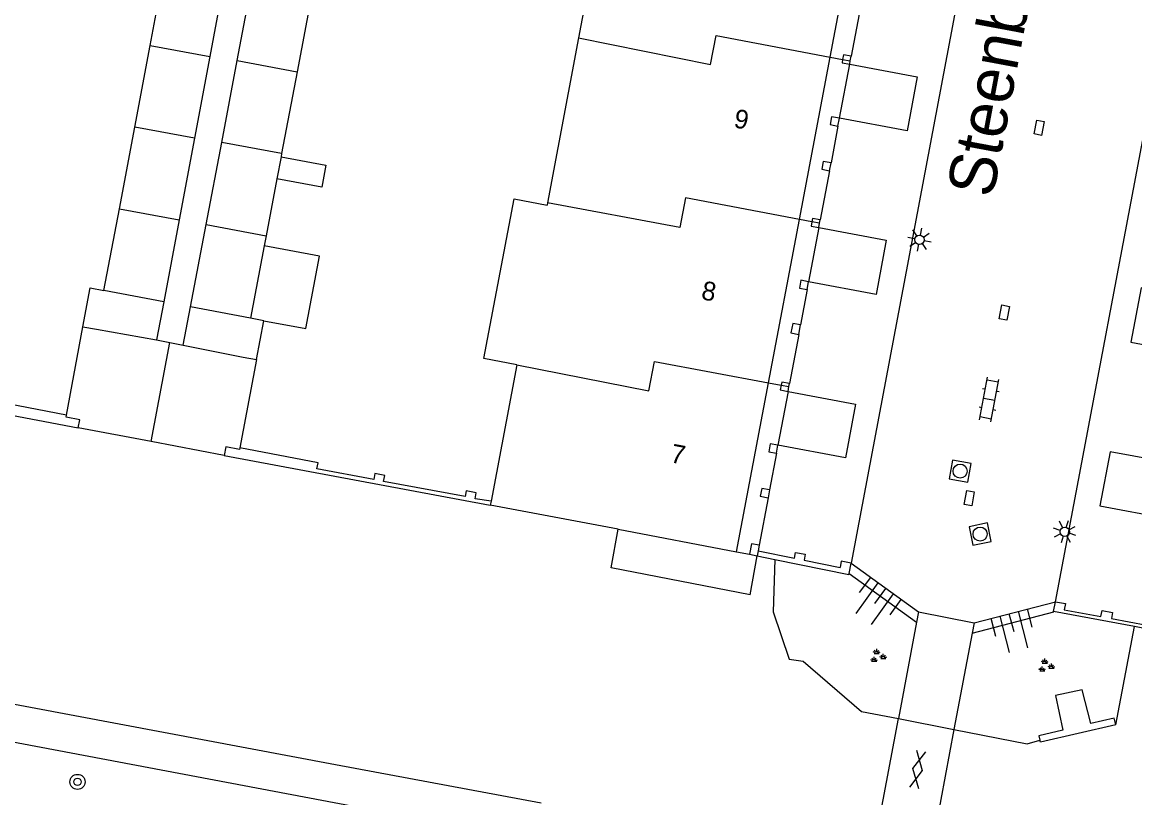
# Model space of a CAD drawing. Extents: x 124000 to 128010, y 398999 to 403000.
# Drawn here: x 126679.1 to 126738.3, y 399098.7 to 399140 of the extents above; entities that cross this region are included whole.
import ezdxf

# ---------------------------------------------------------------- set-up
doc = ezdxf.new("R2010")
doc.units = 0
for name, color, linetype in [('gg-afsc-muur', 7, 'Continuous'), ('gg-anno-huisnummerreeks BGT', 7, 'Continuous'), ('gg-anno-openbare ruimte label', 7, 'Continuous'), ('gg-bbg-bijgebouw', 7, 'Continuous'), ('gg-bbg-gedigitaliseerde bebouwing', 7, 'Continuous'), ('gg-bbg-gedigitaliseerde bijgebouw', 7, 'Continuous'), ('gg-bbg-hoofdgebouw', 7, 'Continuous'), ('gg-bbg-luifel en loopbrug', 7, 'Continuous'), ('gg-bbg-onder overbouw', 7, 'Continuous'), ('gg-bbg-pand overbouw', 7, 'Continuous'), ('gg-bbg-pilaar onder overbouw', 7, 'Continuous'), ('gg-bbg-pilaar pand', 7, 'Continuous'), ('gg-bbg-tussenscheiding', 7, 'Continuous'), ('gg-bbg-tussenscheiding niveau 01', 7, 'Continuous'), ('gg-knt-verharding', 7, 'Continuous'), ('gg-kntw-beschoeiing', 7, 'Continuous'), ('gg-kntw-kademuur', 7, 'Continuous'), ('gg-kwrk-kunstwerk niveau 01', 7, 'Continuous'), ('gg-kwrk-uitstroombak niveau min 01', 7, 'Continuous'), ('gt-grn-groengrens', 7, 'Continuous'), ('gt-symb-boom', 7, 'Continuous'), ('gt-symb-gesloten verharding', 7, 'Continuous'), ('gt-symb-groenvak', 7, 'Continuous'), ('gt-symb-klinker verharding', 7, 'Continuous'), ('gt-symb-kolk center center', 7, 'Continuous'), ('gt-symb-lichtmast', 7, 'Continuous'), ('gt-symb-rioolschacht', 7, 'Continuous'), ('gt-symb-talud symbool', 7, 'Continuous')]:
    doc.layers.add(name, color=color, linetype=linetype)

# ---------------------------------------------------------------- blocks, each defined once
blk = doc.blocks.new('gt0-LMAST')
at = {"layer": 'gt-symb-lichtmast'}
for p, q in [((-0.005, 0.246), (-0.005, 0.621)), ((-0.182, 0.173), (-0.447, 0.438)), ((0.172, 0.173), (0.437, 0.438)), ((-0.255, -0.004), (-0.63, -0.004)), ((-0.182, -0.181), (-0.447, -0.446)), ((-0.005, -0.254), (-0.005, -0.629)), ((0.437, -0.446), (0.172, -0.181)), ((0.245, -0.004), (0.62, -0.004))]:
    blk.add_line(p, q, dxfattribs=at)
blk.add_circle((-0.005, -0.004), 0.25, dxfattribs=at)
blk = doc.blocks.new('gt0-KOLKCC')
at = {"layer": 'gt-symb-kolk center center'}
blk.add_lwpolyline([(-0.375, 0.2), (0.375, 0.2), (0.375, -0.2), (-0.375, -0.2)], close=True, dxfattribs=at)
blk = doc.blocks.new('gt0-BOOM')
at = {"layer": 'gt-symb-boom'}
for radius in [0.4, 0.2]:
    blk.add_circle((0, 0), radius, dxfattribs=at)
blk = doc.blocks.new('gt0-KL1')
at = {"layer": 'gt-symb-klinker verharding'}
for p, q in [((-1.15, 0.3), (1.15, 0.3)), ((-1, -0.3), (-1, 0.3)), ((-0.5, 0.3), (-0.5, 0.45)), ((0, -0.3), (0, 0.3)), ((0.5, 0.3), (0.5, 0.45)), ((1, -0.3), (1, 0.3)), ((-1.15, -0.3), (1.15, -0.3)), ((-0.5, -0.45), (-0.5, -0.3)), ((0.5, -0.45), (0.5, -0.3))]:
    blk.add_line(p, q, dxfattribs=at)
blk = doc.blocks.new('gt0-RS')
at = {"layer": 'gt-symb-rioolschacht'}
blk.add_lwpolyline([(-0.5, -0.5), (0.5, -0.5), (0.5, 0.5), (-0.5, 0.5)], close=True, dxfattribs=at)
blk.add_circle((0, 0), 0.375, dxfattribs=at)
blk = doc.blocks.new('gt0-GESVH1')
at = {"layer": 'gt-symb-gesloten verharding'}
for p, q in [((-0.992, -0.261), (0.008, 0.239)), ((0.008, -0.261), (-0.992, 0.239)), ((0.008, 0.239), (1.008, -0.261)), ((1.008, 0.239), (0.008, -0.261))]:
    blk.add_line(p, q, dxfattribs=at)
blk = doc.blocks.new('gt0-TALUD_1')
at = {"layer": 'gt-symb-talud symbool'}
for p, q in [((-1, -1), (-1, 0)), ((-0.5, -2), (-0.5, 0)), ((0, -1), (0, 0)), ((0.5, -2), (0.5, 0)), ((1, -1), (1, 0))]:
    blk.add_line(p, q, dxfattribs=at)
blk = doc.blocks.new('gt0-GRVAK')
at = {"layer": 'gt-symb-groenvak'}
for p, q in [((-0.11, 0.189), (-0.228, 0.24)), ((-0.182, 0.153), (0.088, 0.153)), ((-0.091, 0.211), (-0.156, 0.322)), ((-0.047, 0.214), (-0.047, 0.393)), ((-0.004, 0.211), (0.061, 0.322)), ((0.015, 0.189), (0.133, 0.24)), ((0.262, -0.052), (0.197, 0.059)), ((0.305, -0.049), (0.305, 0.13)), ((0.349, -0.052), (0.414, 0.059)), ((-0.245, -0.228), (-0.363, -0.177)), ((-0.318, -0.264), (-0.047, -0.264)), ((-0.226, -0.206), (-0.291, -0.095)), ((-0.183, -0.203), (-0.183, -0.024)), ((-0.139, -0.206), (-0.074, -0.095)), ((-0.12, -0.228), (-0.002, -0.177)), ((0.243, -0.074), (0.125, -0.023)), ((0.17, -0.11), (0.441, -0.11)), ((0.368, -0.074), (0.486, -0.023))]:
    blk.add_line(p, q, dxfattribs=at)

msp = doc.modelspace()

# ---------------------------------------------------------------- linework, layer by layer
at = {"layer": 'gg-afsc-muur'}
for p, q in [((126719.141, 399111.407), (126723.075, 399110.606)), ((126720.689, 399111.375), (126722.604, 399110.986)), ((126723.087, 399110.667), (126723.192, 399111.208)), ((126723.075, 399110.606), (126723.087, 399110.667)), ((126733.952, 399108.645), (126734.049, 399109.162)), ((126738.243, 399107.841), (126733.952, 399108.645))]:
    msp.add_line(p, q, dxfattribs=at)
for points in [[(126681.496, 399119.082), (126677.347, 399119.87), (126677.285, 399119.546), (126674.107, 399120.141), (126674.164, 399120.471), (126673.651, 399120.556), (126673.597, 399120.23), (126670.209, 399120.886), (126670.267, 399121.207), (126669.747, 399121.295), (126669.692, 399120.97), (126666.052, 399121.679)], [(126704.06, 399114.5), (126703.213, 399114.633), (126703.26, 399114.958), (126702.735, 399115.064), (126702.686, 399114.749), (126698.345, 399115.549), (126698.413, 399115.872), (126697.891, 399115.981), (126697.829, 399115.657), (126694.804, 399116.229), (126694.875, 399116.541), (126690.707, 399117.344)], [(126718.3, 399112.161), (126717.901, 399112.236), (126717.797, 399111.681)], [(126718.248, 399111.872), (126720.178, 399111.479), (126720.237, 399111.787)], [(126720.237, 399111.787), (126720.751, 399111.682), (126720.689, 399111.375)], [(126723.192, 399111.208), (126722.667, 399111.31), (126722.604, 399110.986)], [(126734.049, 399109.162), (126734.58, 399109.063), (126734.518, 399108.735), (126736.465, 399108.37)], [(126736.465, 399108.37), (126736.533, 399108.697), (126737.085, 399108.593), (126737.023, 399108.266), (126738.904, 399107.913)]]:
    msp.add_lwpolyline(points, dxfattribs=at)
at = {"layer": 'gg-bbg-bijgebouw'}
for p, q in [((126685.128, 399134.399), (126685.947, 399138.742)), ((126689.107, 399138.148), (126688.292, 399133.804)), ((126689.745, 399133.587), (126690.568, 399137.935)), ((126693.748, 399137.337), (126692.929, 399132.988)), ((126683.49, 399125.713), (126684.309, 399130.056)), ((126687.478, 399129.46), (126686.663, 399125.115)), ((126688.088, 399124.835), (126688.917, 399129.211)), ((126692.105, 399128.611), (126692.006, 399128.087)), ((126692.006, 399128.087), (126691.281, 399124.234)), ((126681.496, 399119.082), (126682.374, 399123.784)), ((126686.281, 399123.081), (126686.993, 399122.944)), ((126686.993, 399122.944), (126687.704, 399122.807)), ((126691.597, 399122.045), (126690.707, 399117.344)), ((126686.001, 399117.678), (126682.123, 399118.411)), ((126689.879, 399116.945), (126686.001, 399117.678))]:
    msp.add_line(p, q, dxfattribs=at)
for points in [[(126682.374, 399123.784), (126683.101, 399123.647), (126686.281, 399123.081)], [(126687.704, 399122.807), (126690.893, 399122.17), (126691.597, 399122.045)], [(126682.123, 399118.411), (126682.202, 399118.833), (126681.475, 399118.969), (126681.496, 399119.082)], [(126690.707, 399117.344), (126690.69, 399117.253), (126689.963, 399117.391), (126689.879, 399116.945)]]:
    msp.add_lwpolyline(points, dxfattribs=at)
at = {"layer": 'gg-bbg-gedigitaliseerde bebouwing'}
msp.add_lwpolyline([(126705.436, 399121.752), (126703.676, 399122.086), (126705.289, 399130.588), (126707.039, 399130.256)], dxfattribs=at)
at = {"layer": 'gg-bbg-gedigitaliseerde bijgebouw'}
for p, q in [((126685.947, 399138.742), (126689.107, 399138.148)), ((126690.568, 399137.935), (126693.748, 399137.337)), ((126688.292, 399133.804), (126685.128, 399134.399)), ((126692.929, 399132.988), (126689.745, 399133.587)), ((126684.309, 399130.056), (126687.478, 399129.46)), ((126688.917, 399129.211), (126692.105, 399128.611)), ((126686.663, 399125.115), (126683.49, 399125.713)), ((126691.281, 399124.234), (126688.088, 399124.835))]:
    msp.add_line(p, q, dxfattribs=at)
at = {"layer": 'gg-bbg-hoofdgebouw'}
for p, q in [((126708.712, 399139.147), (126707.062, 399130.38)), ((126707.062, 399130.38), (126707.039, 399130.256)), ((126705.436, 399121.752), (126704.06, 399114.5)), ((126704.06, 399114.5), (126704.02, 399114.287)), ((126710.807, 399113.011), (126704.02, 399114.287))]:
    msp.add_line(p, q, dxfattribs=at)
msp.add_lwpolyline([(126712.386, 399147.269), (126710.3, 399147.585), (126708.712, 399139.147)], dxfattribs=at)
at = {"layer": 'gg-bbg-luifel en loopbrug'}
for p, q in [((126685.947, 399138.742), (126686.766, 399143.085)), ((126689.921, 399142.491), (126689.107, 399138.148)), ((126690.568, 399137.935), (126691.391, 399142.283)), ((126694.566, 399141.686), (126693.748, 399137.337)), ((126684.309, 399130.056), (126685.128, 399134.399)), ((126688.292, 399133.804), (126687.478, 399129.46)), ((126688.917, 399129.211), (126689.745, 399133.587)), ((126692.898, 399132.825), (126692.678, 399131.654)), ((126692.929, 399132.988), (126692.898, 399132.825)), ((126692.678, 399131.654), (126692.105, 399128.611)), ((126686.663, 399125.115), (126686.281, 399123.081)), ((126687.704, 399122.807), (126688.088, 399124.835)), ((126691.982, 399124.103), (126691.281, 399124.234)), ((126691.597, 399122.045), (126691.982, 399124.103))]:
    msp.add_line(p, q, dxfattribs=at)
for points in [[(126723.118, 399137.747), (126726.706, 399137.077), (126726.169, 399134.201), (126722.574, 399134.872)], [(126692.898, 399132.825), (126695.282, 399132.376), (126695.062, 399131.206), (126692.678, 399131.654)], [(126721.476, 399129.052), (126725.064, 399128.382), (126724.527, 399125.505), (126720.934, 399126.176)], [(126691.982, 399124.103), (126694.211, 399123.682), (126694.939, 399127.533), (126692.006, 399128.087)], [(126682.374, 399123.784), (126682.76, 399125.849), (126683.49, 399125.713)], [(126742.189, 399125.174), (126738.601, 399125.845), (126738.063, 399122.964), (126741.644, 399122.295)], [(126719.843, 399120.344), (126723.431, 399119.674), (126722.896, 399116.807), (126719.303, 399117.478)], [(126740.544, 399116.468), (126736.956, 399117.139), (126736.418, 399114.259), (126740.001, 399113.589)]]:
    msp.add_lwpolyline(points, dxfattribs=at)
at = {"layer": 'gg-bbg-onder overbouw'}
for p, q in [((126722.085, 399138.125), (126723.744, 399146.899)), ((126720.452, 399129.488), (126722.085, 399138.125)), ((126718.808, 399120.802), (126720.452, 399129.488)), ((126717.11, 399111.821), (126718.808, 399120.802)), ((126710.807, 399113.011), (126717.11, 399111.821))]:
    msp.add_line(p, q, dxfattribs=at)
at = {"layer": 'gg-bbg-pand overbouw'}
for p, q in [((126723.688, 399140.784), (126723.194, 399138.163)), ((126722.574, 399134.872), (126723.118, 399137.747)), ((126722.495, 399134.456), (126722.125, 399132.494)), ((126722.047, 399132.078), (126721.555, 399129.468)), ((126721.476, 399129.052), (126720.934, 399126.176)), ((126720.862, 399125.759), (126720.509, 399123.885)), ((126720.413, 399123.373), (126719.921, 399120.76)), ((126719.843, 399120.344), (126719.303, 399117.478)), ((126719.225, 399117.062), (126718.856, 399115.104)), ((126718.777, 399114.688), (126718.3, 399112.161)), ((126718.248, 399111.872), (126718.198, 399111.599)), ((126718.3, 399112.161), (126718.248, 399111.872)), ((126717.825, 399109.532), (126718.198, 399111.599))]:
    msp.add_line(p, q, dxfattribs=at)
msp.add_lwpolyline([(126717.825, 399109.532), (126710.434, 399110.959), (126710.807, 399113.011)], dxfattribs=at)
at = {"layer": 'gg-bbg-pilaar onder overbouw'}
for points in [[(126722.74, 399138.002), (126722.709, 399137.824), (126723.118, 399137.747)], [(126723.194, 399138.163), (126722.781, 399138.241), (126722.74, 399138.002)], [(126722.574, 399134.872), (126722.154, 399134.951), (126722.082, 399134.534), (126722.495, 399134.456)], [(126722.125, 399132.494), (126721.706, 399132.573), (126721.634, 399132.156), (126722.047, 399132.078)], [(126721.555, 399129.468), (126721.135, 399129.547), (126721.104, 399129.365)], [(126721.104, 399129.365), (126721.063, 399129.13), (126721.476, 399129.052)], [(126720.934, 399126.176), (126720.521, 399126.254), (126720.449, 399125.837), (126720.862, 399125.759)], [(126720.509, 399123.885), (126720.09, 399123.964), (126719.994, 399123.452), (126720.413, 399123.373)], [(126719.477, 399120.676), (126719.43, 399120.422), (126719.843, 399120.344)], [(126719.921, 399120.76), (126719.508, 399120.838), (126719.477, 399120.676)], [(126719.303, 399117.478), (126718.89, 399117.556), (126718.812, 399117.14), (126719.225, 399117.062)], [(126718.856, 399115.104), (126718.443, 399115.182), (126718.365, 399114.769), (126718.777, 399114.688)]]:
    msp.add_lwpolyline(points, dxfattribs=at)
at = {"layer": 'gg-bbg-pilaar pand'}
for p, q in [((126723.118, 399137.747), (126723.15, 399137.924)), ((126723.15, 399137.924), (126723.194, 399138.163)), ((126722.495, 399134.456), (126722.574, 399134.872)), ((126722.047, 399132.078), (126722.125, 399132.494)), ((126721.476, 399129.052), (126721.521, 399129.286)), ((126721.521, 399129.286), (126721.555, 399129.468)), ((126720.862, 399125.759), (126720.934, 399126.176)), ((126720.413, 399123.373), (126720.509, 399123.885)), ((126719.891, 399120.598), (126719.921, 399120.76)), ((126719.843, 399120.344), (126719.891, 399120.598)), ((126719.225, 399117.062), (126719.303, 399117.478)), ((126718.856, 399115.104), (126718.777, 399114.688))]:
    msp.add_line(p, q, dxfattribs=at)
at = {"layer": 'gg-bbg-tussenscheiding'}
msp.add_line((126686.001, 399117.678), (126686.993, 399122.944), dxfattribs=at)
for points in [[(126708.712, 399139.147), (126715.729, 399137.722), (126716.021, 399139.265), (126722.085, 399138.125)], [(126720.452, 399129.488), (126714.387, 399130.629), (126714.091, 399129.057), (126707.062, 399130.38)], [(126705.436, 399121.752), (126712.45, 399120.381), (126712.745, 399121.943), (126718.808, 399120.802)]]:
    msp.add_lwpolyline(points, dxfattribs=at)
at = {"layer": 'gg-bbg-tussenscheiding niveau 01'}
for p, q in [((126722.085, 399138.125), (126722.74, 399138.002)), ((126722.74, 399138.002), (126723.15, 399137.924)), ((126721.104, 399129.365), (126720.452, 399129.488)), ((126721.521, 399129.286), (126721.104, 399129.365)), ((126718.808, 399120.802), (126719.477, 399120.676)), ((126719.477, 399120.676), (126719.891, 399120.598))]:
    msp.add_line(p, q, dxfattribs=at)
at = {"layer": 'gg-knt-verharding'}
for p, q in [((126732.641, 399161.4), (126723.192, 399111.208)), ((126734.049, 399109.162), (126743.527, 399159.36)), ((126723.192, 399111.208), (126726.77, 399108.615)), ((126729.723, 399108.036), (126734.049, 399109.162))]:
    msp.add_line(p, q, dxfattribs=at)
at = {"layer": 'gg-kntw-beschoeiing'}
for p, q in [((126737.265, 399102.62), (126738.243, 399107.841)), ((126725.703, 399102.945), (126728.657, 399102.366)), ((126695.8, 399100.513), (126706.72, 399098.46))]:
    msp.add_line(p, q, dxfattribs=at)
for points in [[(126578.996, 399125.563), (126578.936, 399124.779), (126582.896, 399121.736), (126695.8, 399100.513)], [(126719.141, 399111.407), (126719.053, 399108.616), (126719.908, 399106.103), (126720.641, 399106.002), (126723.743, 399103.329), (126725.703, 399102.945)], [(126728.657, 399102.366), (126732.545, 399101.604), (126733.227, 399101.808)]]:
    msp.add_lwpolyline(points, dxfattribs=at)
at = {"layer": 'gg-kntw-kademuur'}
for p, q in [((126666.01, 399121.456), (126682.123, 399118.411)), ((126689.879, 399116.945), (126704.02, 399114.287)), ((126717.11, 399111.821), (126717.797, 399111.681)), ((126717.797, 399111.681), (126718.198, 399111.599)), ((126718.198, 399111.599), (126719.141, 399111.407)), ((126738.867, 399107.724), (126738.243, 399107.841))]:
    msp.add_line(p, q, dxfattribs=at)
at = {"layer": 'gg-kwrk-kunstwerk niveau 01'}
for p, q in [((126726.77, 399108.615), (126726.668, 399108.072)), ((126726.77, 399108.615), (126729.723, 399108.036)), ((126726.668, 399108.072), (126725.703, 399102.945)), ((126729.723, 399108.036), (126729.621, 399107.493)), ((126729.621, 399107.493), (126728.657, 399102.366)), ((126724.616, 399097.16), (126725.703, 399102.945)), ((126728.657, 399102.366), (126727.572, 399096.584))]:
    msp.add_line(p, q, dxfattribs=at)
at = {"layer": 'gg-kwrk-uitstroombak niveau min 01'}
for points in [[(126737.265, 399102.62), (126737.172, 399102.97), (126735.936, 399102.68), (126735.47, 399104.481), (126734.05, 399104.176), (126734.447, 399102.331), (126733.174, 399102.033), (126733.227, 399101.808)], [(126737.265, 399102.62), (126733.252, 399101.7), (126733.227, 399101.808)]]:
    msp.add_lwpolyline(points, dxfattribs=at)
at = {"layer": 'gt-grn-groengrens'}
msp.add_line((126723.087, 399110.667), (126726.668, 399108.072), dxfattribs=at)
for points in [[(126579.161, 399131.587), (126578.169, 399131.203), (126576.802, 399124.502), (126582.49, 399119.877), (126717.58, 399094.355), (126722.431, 399095.972), (126724.333, 399095.654)], [(126729.621, 399107.493), (126733.958, 399108.622), (126733.952, 399108.645)]]:
    msp.add_lwpolyline(points, dxfattribs=at)

# ---------------------------------------------------------------- block references
at = {"layer": 'gt-symb-boom'}
msp.add_blockref('gt0-BOOM', (126682.083, 399099.582), dxfattribs=at)
at = {"layer": 'gt-symb-gesloten verharding', "rotation": 79.45426563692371}
msp.add_blockref('gt0-GESVH1', (126726.714, 399100.233), dxfattribs=at)
at = {"layer": 'gt-symb-groenvak'}
for p in [(126724.599, 399106.256), (126733.533, 399105.743)]:
    msp.add_blockref('gt0-GRVAK', p, dxfattribs=at)
at = {"layer": 'gt-symb-klinker verharding', "rotation": 79.34163849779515}
msp.add_blockref('gt0-KL1', (126730.53, 399119.911), dxfattribs=at)
at = {"layer": 'gt-symb-kolk center center'}
for p, rotation in [((126733.189, 399134.366), 79.34163849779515), ((126731.334, 399124.536), 79.16208955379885), ((126729.474, 399114.67), 79.34163849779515)]:
    msp.add_blockref('gt0-KOLKCC', p, dxfattribs=dict(at, rotation=rotation))
at = {"layer": 'gt-symb-lichtmast'}
for p, rotation in [((126726.828, 399128.405), -100.78161673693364), ((126734.548, 399112.884), 26.744420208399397)]:
    msp.add_blockref('gt0-LMAST', p, dxfattribs=dict(at, rotation=rotation))
at = {"layer": 'gt-symb-rioolschacht'}
for p, rotation in [((126728.987, 399116.104), 79.80279442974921), ((126730.047, 399112.758), 101.42232107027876)]:
    msp.add_blockref('gt0-RS', p, dxfattribs=dict(at, rotation=rotation))
at = {"layer": 'gt-symb-talud symbool'}
for p, xscale, yscale, rotation in [((126725.042, 399109.868), 1.0003344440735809, 1.0003344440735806, -35.93051893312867), ((126731.597, 399108.524), 1.0002639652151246, 1.000263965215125, 14.591956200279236)]:
    msp.add_blockref('gt0-TALUD_1', p, dxfattribs=dict(at, xscale=xscale, yscale=yscale, rotation=rotation))

# ---------------------------------------------------------------- texts
at = {"layer": 'gg-anno-huisnummerreeks BGT'}
for s, p in [('9', (126716.913, 399134.394)), ('8', (126715.184, 399125.254)), ('7', (126713.544, 399116.583))]:
    msp.add_text(s, height=1, rotation=349.3, dxfattribs=at).set_placement(p)
at = {"layer": 'gg-anno-openbare ruimte label'}
msp.add_text('Steenbergenerf', height=2.5, rotation=79.4, dxfattribs=at).set_placement((126730.72, 399130.578))

doc.saveas('drawing.dxf')
